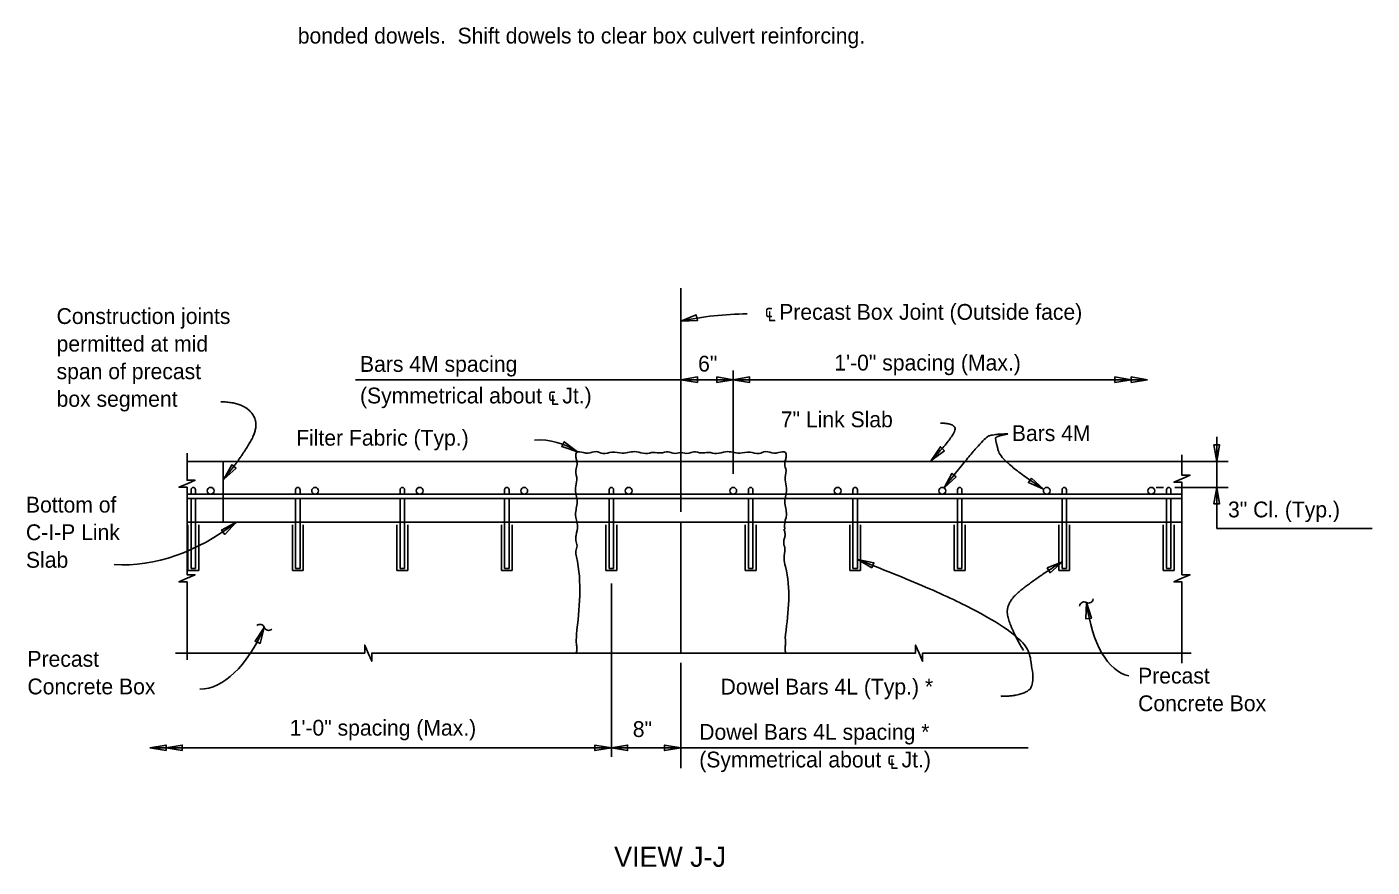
# Model space of a CAD drawing. Extents: x 10691 to 11555, y 76323 to 76455.
# Drawn here: x 10691.12 to 10703.99, y 76430.94 to 76438.98 of the extents above; entities that cross this region are included whole.
import ezdxf

# ---------------------------------------------------------------- set-up
doc = ezdxf.new("R2010")
doc.units = 0
for name, color, linetype in [('AdhocPoint_dp', 7, 'Continuous'), ('Border', 7, 'Continuous'), ('Patterning', 7, 'Continuous'), ('PlotBorder_dp', 7, 'Continuous'), ('SheetBorder_dp', 7, 'Continuous'), ('SheetLines_dp', 7, 'Continuous'), ('TextMisc', 7, 'Continuous')]:
    doc.layers.add(name, color=color, linetype=linetype)

msp = doc.modelspace()

# ---------------------------------------------------------------- linework, layer by layer
at = {"layer": 'AdhocPoint_dp'}
for p, q in [((10692.693, 76434.552), (10692.693, 76434.507)), ((10692.735, 76434.552), (10692.735, 76434.507)), ((10693.693, 76434.552), (10693.693, 76434.507)), ((10693.735, 76434.552), (10693.735, 76434.507)), ((10694.693, 76434.552), (10694.693, 76434.507)), ((10694.735, 76434.552), (10694.735, 76434.507)), ((10695.693, 76434.552), (10695.693, 76434.507)), ((10695.735, 76434.552), (10695.735, 76434.507)), ((10696.693, 76434.552), (10696.693, 76434.507)), ((10696.735, 76434.552), (10696.735, 76434.507)), ((10698.026, 76434.552), (10698.026, 76434.507)), ((10698.068, 76434.552), (10698.068, 76434.507)), ((10699.026, 76434.552), (10699.026, 76434.507)), ((10699.068, 76434.552), (10699.068, 76434.507)), ((10700.026, 76434.552), (10700.026, 76434.507)), ((10700.068, 76434.552), (10700.068, 76434.507)), ((10701.026, 76434.552), (10701.026, 76434.507)), ((10701.068, 76434.552), (10701.068, 76434.507)), ((10702.026, 76434.552), (10702.026, 76434.507)), ((10702.068, 76434.552), (10702.068, 76434.507)), ((10692.654, 76434.507), (10702.173, 76434.507)), ((10692.654, 76434.465), (10702.173, 76434.465)), ((10692.693, 76434.465), (10692.693, 76433.798)), ((10692.735, 76434.465), (10692.735, 76433.798)), ((10693.693, 76434.465), (10693.693, 76433.798)), ((10693.735, 76434.465), (10693.735, 76433.798)), ((10694.693, 76434.465), (10694.693, 76433.798)), ((10694.735, 76434.465), (10694.735, 76433.798)), ((10695.693, 76434.465), (10695.693, 76433.798)), ((10695.735, 76434.465), (10695.735, 76433.798)), ((10696.693, 76434.465), (10696.693, 76433.798)), ((10696.735, 76434.465), (10696.735, 76433.798)), ((10698.026, 76434.465), (10698.026, 76433.798)), ((10698.068, 76434.465), (10698.068, 76433.798)), ((10699.026, 76434.465), (10699.026, 76433.798)), ((10699.068, 76434.465), (10699.068, 76433.798)), ((10700.026, 76434.465), (10700.026, 76433.798)), ((10700.068, 76434.465), (10700.068, 76433.798)), ((10701.026, 76434.465), (10701.026, 76433.798)), ((10701.068, 76434.465), (10701.068, 76433.798)), ((10702.026, 76434.465), (10702.026, 76433.798)), ((10702.068, 76434.465), (10702.068, 76433.798)), ((10692.693, 76433.798), (10692.735, 76433.798)), ((10692.735, 76433.798), (10692.693, 76433.798)), ((10693.693, 76433.798), (10693.735, 76433.798)), ((10693.735, 76433.798), (10693.693, 76433.798)), ((10694.693, 76433.798), (10694.735, 76433.798)), ((10694.735, 76433.798), (10694.693, 76433.798)), ((10695.693, 76433.798), (10695.735, 76433.798)), ((10695.735, 76433.798), (10695.693, 76433.798)), ((10696.693, 76433.798), (10696.735, 76433.798)), ((10696.735, 76433.798), (10696.693, 76433.798)), ((10698.068, 76433.798), (10698.026, 76433.798)), ((10698.026, 76433.798), (10698.068, 76433.798)), ((10699.068, 76433.798), (10699.026, 76433.798)), ((10699.026, 76433.798), (10699.068, 76433.798)), ((10700.068, 76433.798), (10700.026, 76433.798)), ((10700.026, 76433.798), (10700.068, 76433.798)), ((10701.068, 76433.798), (10701.026, 76433.798)), ((10701.026, 76433.798), (10701.068, 76433.798)), ((10702.068, 76433.798), (10702.026, 76433.798)), ((10702.026, 76433.798), (10702.068, 76433.798))]:
    msp.add_line(p, q, dxfattribs=at)
for centre in [(10692.88, 76434.54), (10693.88, 76434.54), (10694.88, 76434.54), (10695.88, 76434.54), (10696.88, 76434.54), (10697.88, 76434.54), (10698.88, 76434.54), (10699.88, 76434.54), (10700.88, 76434.54), (10701.88, 76434.54)]:
    msp.add_circle(centre, 0.0328, dxfattribs=at)
for centre in [(10692.714, 76434.552), (10693.714, 76434.552), (10694.714, 76434.552), (10695.714, 76434.552), (10696.714, 76434.552), (10698.047, 76434.552), (10699.047, 76434.552), (10700.047, 76434.552), (10701.047, 76434.552), (10702.047, 76434.552)]:
    msp.add_arc(centre, 0.0209, 0, 180, dxfattribs=at)
at = {"layer": 'Border'}
for p, q in [((10697.38, 76436.479), (10697.38, 76434.339)), ((10697.38, 76432.894), (10697.38, 76431.886))]:
    msp.add_line(p, q, dxfattribs=at)
at = {"layer": 'PlotBorder_dp'}
for p, q in [((10692.654, 76434.822), (10697.38, 76434.822)), ((10702.173, 76434.822), (10697.38, 76434.822)), ((10692.654, 76434.239), (10697.38, 76434.239)), ((10702.173, 76434.239), (10697.38, 76434.239))]:
    msp.add_line(p, q, dxfattribs=at)
at = {"layer": 'SheetBorder_dp'}
for p, q in [((10693, 76434.822), (10693, 76434.239)), ((10692.662, 76434.215), (10692.662, 76433.778)), ((10692.766, 76434.215), (10692.766, 76433.778)), ((10693.662, 76434.215), (10693.662, 76433.778)), ((10693.766, 76434.215), (10693.766, 76433.778)), ((10694.662, 76434.215), (10694.662, 76433.778)), ((10694.766, 76434.215), (10694.766, 76433.778)), ((10695.662, 76434.215), (10695.662, 76433.778)), ((10695.766, 76434.215), (10695.766, 76433.778)), ((10696.662, 76434.215), (10696.662, 76433.778)), ((10696.766, 76434.215), (10696.766, 76433.778)), ((10697.38, 76434.239), (10697.38, 76432.997)), ((10697.995, 76434.215), (10697.995, 76433.778)), ((10698.099, 76434.215), (10698.099, 76433.778)), ((10698.995, 76434.215), (10698.995, 76433.778)), ((10699.099, 76434.215), (10699.099, 76433.778)), ((10699.995, 76434.215), (10699.995, 76433.778)), ((10700.099, 76434.215), (10700.099, 76433.778)), ((10700.995, 76434.215), (10700.995, 76433.778)), ((10701.099, 76434.215), (10701.099, 76433.778)), ((10701.995, 76434.215), (10701.995, 76433.778)), ((10702.099, 76434.215), (10702.099, 76433.778)), ((10692.662, 76433.778), (10692.766, 76433.778)), ((10693.662, 76433.778), (10693.766, 76433.778)), ((10694.662, 76433.778), (10694.766, 76433.778)), ((10695.662, 76433.778), (10695.766, 76433.778)), ((10696.662, 76433.778), (10696.766, 76433.778)), ((10698.099, 76433.778), (10697.995, 76433.778)), ((10699.099, 76433.778), (10698.995, 76433.778)), ((10700.099, 76433.778), (10699.995, 76433.778)), ((10701.099, 76433.778), (10700.995, 76433.778)), ((10702.099, 76433.778), (10701.995, 76433.778))]:
    msp.add_line(p, q, dxfattribs=at)
at = {"layer": 'SheetLines_dp'}
for points in [[(10697.38, 76434.906), (10697.305, 76434.9), (10697.259, 76434.912), (10697.185, 76434.902), (10697.118, 76434.907), (10697.04, 76434.897), (10696.954, 76434.914), (10696.819, 76434.9), (10696.719, 76434.909), (10696.634, 76434.898), (10696.57, 76434.915), (10696.492, 76434.9), (10696.447, 76434.905), (10696.38, 76434.906), (10696.374, 76434.869), (10696.38, 76434.838), (10696.387, 76434.796), (10696.375, 76434.734), (10696.384, 76434.645), (10696.37, 76434.566), (10696.387, 76434.434), (10696.372, 76434.311), (10696.391, 76434.207), (10696.377, 76434.114), (10696.375, 76434.064), (10696.386, 76434.013), (10696.374, 76433.962), (10696.38, 76433.909), (10696.38, 76433.165)], [(10697.38, 76434.906), (10697.456, 76434.9), (10697.502, 76434.912), (10697.575, 76434.902), (10697.642, 76434.907), (10697.721, 76434.897), (10697.807, 76434.914), (10697.942, 76434.9), (10698.041, 76434.909), (10698.127, 76434.898), (10698.19, 76434.915), (10698.269, 76434.9), (10698.313, 76434.905), (10698.38, 76434.906), (10698.387, 76434.869), (10698.38, 76434.838), (10698.373, 76434.796), (10698.385, 76434.734), (10698.377, 76434.645), (10698.391, 76434.566), (10698.373, 76434.434), (10698.389, 76434.311), (10698.37, 76434.207), (10698.374, 76434.173)], [(10698.364, 76434.173), (10698.37, 76434.156), (10698.377, 76434.119), (10698.37, 76434.088), (10698.363, 76434.046), (10698.375, 76433.984), (10698.366, 76433.895), (10698.38, 76433.816), (10698.381, 76433.165)], [(10696.38, 76433.165), (10696.38, 76433.159), (10696.38, 76433.072), (10696.384, 76433.033), (10696.379, 76432.987)], [(10698.381, 76433.165), (10698.38, 76433.159), (10698.38, 76433.072), (10698.376, 76433.033), (10698.382, 76432.987)]]:
    msp.add_spline(points, degree=3, dxfattribs=at)
at = {"layer": 'TextMisc'}
for p, q in [((10697.88, 76435.69), (10697.88, 76434.701)), ((10694.266, 76435.603), (10697.38, 76435.603)), ((10697.38, 76435.603), (10701.844, 76435.603)), ((10702.506, 76435.058), (10702.506, 76434.18)), ((10702.158, 76434.822), (10702.617, 76434.822)), ((10701.927, 76434.572), (10701.998, 76434.572)), ((10702.104, 76434.572), (10702.617, 76434.572)), ((10702.506, 76434.18), (10703.993, 76434.18)), ((10696.714, 76431.995), (10696.714, 76433.652)), ((10697.38, 76432.082), (10692.297, 76432.082)), ((10697.38, 76432.082), (10700.703, 76432.082))]:
    msp.add_line(p, q, dxfattribs=at)
for points in [[(10697.38, 76436.163), (10697.527, 76436.222), (10697.539, 76436.17)], [(10697.38, 76435.603), (10697.537, 76435.577), (10697.537, 76435.63)], [(10697.88, 76435.603), (10697.724, 76435.63), (10697.724, 76435.577)], [(10697.88, 76435.603), (10698.036, 76435.577), (10698.036, 76435.63)], [(10701.688, 76435.603), (10701.532, 76435.63), (10701.532, 76435.577)], [(10701.844, 76435.603), (10701.688, 76435.63), (10701.688, 76435.577)], [(10696.39, 76434.912), (10696.264, 76435.009), (10696.239, 76434.963)], [(10699.9, 76434.924), (10699.773, 76434.829), (10699.862, 76434.961)], [(10702.506, 76434.822), (10702.48, 76434.979), (10702.533, 76434.979)], [(10693.125, 76434.757), (10693.006, 76434.652), (10693.084, 76434.79)], [(10700.014, 76434.674), (10699.897, 76434.567), (10699.972, 76434.707)], [(10700.733, 76434.662), (10700.85, 76434.555), (10700.704, 76434.618)], [(10702.506, 76434.572), (10702.48, 76434.416), (10702.533, 76434.416)], [(10693.124, 76434.239), (10692.984, 76434.165), (10693.016, 76434.123)], [(10699.207, 76433.803), (10699.071, 76433.884), (10699.226, 76433.852)], [(10700.883, 76433.802), (10701.029, 76433.862), (10700.911, 76433.757)], [(10701.259, 76433.472), (10701.254, 76433.314), (10701.307, 76433.321)], [(10693.393, 76433.234), (10693.305, 76433.102), (10693.353, 76433.08)], [(10692.297, 76432.082), (10692.453, 76432.056), (10692.453, 76432.108)], [(10692.453, 76432.082), (10692.609, 76432.056), (10692.609, 76432.108)], [(10696.714, 76432.082), (10696.557, 76432.108), (10696.557, 76432.055)], [(10696.714, 76432.082), (10696.87, 76432.055), (10696.87, 76432.108)], [(10697.38, 76432.082), (10697.224, 76432.108), (10697.224, 76432.055)]]:
    msp.add_lwpolyline(points, close=True, dxfattribs=at)
for points in [[(10692.654, 76434.239), (10692.654, 76434.574), (10692.576, 76434.574), (10692.654, 76434.608), (10692.731, 76434.641), (10692.654, 76434.641), (10692.654, 76434.9)], [(10702.173, 76434.239), (10702.173, 76434.622), (10702.096, 76434.622), (10702.173, 76434.655), (10702.251, 76434.689), (10702.173, 76434.689), (10702.173, 76434.883)], [(10692.654, 76432.924), (10692.654, 76433.669), (10692.576, 76433.669), (10692.654, 76433.703), (10692.731, 76433.737), (10692.654, 76433.737), (10692.654, 76434.239)], [(10702.173, 76432.892), (10702.173, 76433.669), (10702.096, 76433.669), (10702.173, 76433.703), (10702.251, 76433.737), (10702.173, 76433.737), (10702.173, 76434.239)], [(10692.545, 76432.987), (10694.354, 76432.987), (10694.354, 76433.065), (10694.388, 76432.987), (10694.422, 76432.91), (10694.422, 76432.987), (10697.38, 76432.987)], [(10697.38, 76432.987), (10699.625, 76432.987), (10699.625, 76433.065), (10699.658, 76432.987), (10699.692, 76432.91), (10699.692, 76432.987), (10702.261, 76432.987)]]:
    msp.add_lwpolyline(points, dxfattribs=at)
for centre, radius, start, end in [((10698.022, 76433.195), 3.037, 90.1862, 102.1882), ((10696.018, 76434.369), 0.658, 55.6058, 93.4311), ((10701.28, 76433.511), 0.0447, 241.6836, 353.4108), ((10701.238, 76433.433), 0.0447, 61.6836, 173.4108), ((10693.351, 76433.218), 0.0447, 19.8148, 131.542), ((10693.435, 76433.249), 0.0447, 199.8148, 311.542)]:
    msp.add_arc(centre, radius, start, end, dxfattribs=at)
for centre, major_axis, ratio, start_param, end_param in [((10692.118, 76442.131), (0.099, 8.299), 0.422031, 3.123668, 3.460947), ((10702.092, 76434.661), (0.427, 1.891), 0.393692, 2.335904, 3.141593), ((10692.715, 76435.328), (-0.061, 2.686), 0.379091, 3.141593, 3.809705)]:
    msp.add_ellipse(centre, major_axis=major_axis, ratio=ratio, start_param=start_param, end_param=end_param, dxfattribs=at)
for points in [[(10692.978, 76435.391), (10693.184, 76435.391), (10693.359, 76435.18), (10693.165, 76434.847), (10693.006, 76434.652)], [(10699.864, 76435.187), (10700.003, 76435.187), (10700.003, 76435.072), (10699.773, 76434.829)], [(10700.509, 76435.084), (10700.388, 76435.084), (10700.269, 76435.048), (10699.897, 76434.567)], [(10700.509, 76435.084), (10700.39, 76435.062), (10700.39, 76435.024), (10700.443, 76434.82), (10700.85, 76434.555)], [(10700.441, 76432.574), (10700.635, 76432.574), (10700.786, 76432.697), (10700.628, 76433.284), (10699.071, 76433.884)], [(10700.656, 76433.014), (10700.556, 76433.181), (10700.469, 76433.451), (10700.751, 76433.689), (10701.029, 76433.862)]]:
    msp.add_open_spline(points, degree=2, dxfattribs=at)

# ---------------------------------------------------------------- texts
at = {"layer": 'Patterning'}
for s, p in [('1\'-0" spacing (Max.)', (10698.847, 76435.691)), ('Bars 4M', (10700.546, 76435.016)), ('Filter Fabric (Typ.)', (10693.698, 76434.972)), ('Precast', (10691.127, 76432.857)), ('Concrete Box', (10691.127, 76432.593)), ('Dowel Bars 4L (Typ.) *', (10697.759, 76432.591)), ('Precast', (10701.754, 76432.696)), ('Concrete Box', (10701.754, 76432.432)), ('1\'-0" spacing (Max.)', (10693.636, 76432.198))]:
    msp.add_text(s, height=0.1512, dxfattribs=at).set_placement(p)
at = {"layer": 'TextMisc'}
for s, height, p in [('    bonded dowels.  Shift dowels to clear box culvert reinforcing.', 0.1512, (10693.489, 76438.819)), ('℄ Precast Box Joint (Outside face)', 0.1512, (10698.182, 76436.176)), ('Construction joints', 0.1512, (10691.406, 76436.136)), ('permitted at mid', 0.1512, (10691.406, 76435.872)), ('Bars 4M spacing ', 0.1512, (10694.309, 76435.678)), ('6"', 0.1512, (10697.544, 76435.681)), ('span of precast', 0.1512, (10691.406, 76435.608)), ('box segment', 0.1512, (10691.406, 76435.344)), ('(Symmetrical about ℄ Jt.)', 0.1512, (10694.309, 76435.376)), ('7" Link Slab', 0.1512, (10698.335, 76435.148)), ('Bottom of', 0.1512, (10691.113, 76434.332)), ('3" Cl. (Typ.)', 0.1512, (10702.614, 76434.286)), ('C-I-P Link', 0.1512, (10691.113, 76434.068)), ('Slab', 0.1512, (10691.113, 76433.804)), ('8"', 0.1512, (10696.919, 76432.185)), ('Dowel Bars 4L spacing *', 0.1512, (10697.555, 76432.158)), ('(Symmetrical about ℄ Jt.)', 0.1512, (10697.555, 76431.894)), ('VIEW J-J', 0.192, (10696.741, 76430.943))]:
    msp.add_text(s, height=height, dxfattribs=at).set_placement(p)

doc.saveas('drawing.dxf')
